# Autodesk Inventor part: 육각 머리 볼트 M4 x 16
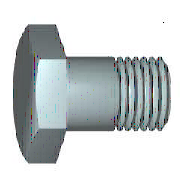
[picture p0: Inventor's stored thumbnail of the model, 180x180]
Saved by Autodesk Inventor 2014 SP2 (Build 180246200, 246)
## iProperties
IsCustomPart: 0
Created: 2012-02
Part Number: 육각 머리 볼트 M4 x 16
Material: 강철, 연강
Description: 6각 머리 볼트 및 6각 머리 나사
Document SubType Name: Modeling
Standard: KS B 1002
Designer: mduedu
Standards Organization: KS
Language: ko-KR
Size Designation: A + B M4 x 16
Categories: <MemberInstance><Categories><Category DisplayName="조임쇠" InternalName="e4da775c-781d-43d5-af7c-5136215cf5a6" Mnemonic="FSTN"><Category DisplayName="볼트" InternalN
Density: 7.86 g/cm^3
Appearance: 강철
Mass: 2.45486 g
Surface Area: 3.4613 cm^2
Volume: 0.312323 cm^3
Author: mduedu
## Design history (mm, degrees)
sketch "스케치1"
  geometry: L1 (0, 2.94)-(0, 2); L2 (2.1, 2)-(16, 2); L3 (16, 2)-(16, 0); L4 (16, 0)-(-0.4, 0); L5 (-3.68, 0)-(19.28, 0) reference; L6 (-0.4, 0)-(-0.4, 2.94); L7 (-0.4, 2.94)-(0, 2.94); L8 (2.1, 2)-(1.67, 2); L9 (1.67, 2)-(0, 2); L10 (0, -0.588)-(0, 3.528) reference
  constraints: 16 end point, 2 collinear, 2 perpendicular, 1 parallel
  dimensions: "d0" = 16 distance between parallel lines of L3 L1 (= NLG); "d1" = 13.9 distance from line of L2.start L3 (= GEL); "d2" = 4 diameter of L2 L4 (= GD); "d9" = 0.4001 distance between parallel lines of L6 L1 (computed from SD); "d10" = 5.88 diameter of L7 L4 (= SD2); "d13" = 0.42952 distance of L2.start L8.end (computed from GAL); "d14" = 4 diameter of L9 L4 (= BDM)
revolve "본체" sketch "스케치1" stored, may be unused: angle "d12" = 90 deg
sketch "스케치2"
  geometry: L1 (0, 4.041)-(3.5, 2.021); L2 (3.5, 2.021)-(3.5, -2.021); L3 (3.5, -2.021)-(0, -4.041); L4 (0, -4.041)-(-3.5, -2.021); L5 (-3.5, -2.021)-(-3.5, 2.021); L6 (-3.5, 2.021)-(0, 4.041); 2 further points
  constraints: 12 end point, 1 coincident, 1 vertical, 11 other
  dimensions: "d11" = 7 distance between parallel lines of L5 L2 (= SW)
extrude "머리" join sketch "스케치2" distance "d3" = 2.4 (= KOH - SD); taper "d4" = 0 deg
sketch "스케치4"
  geometry: L1 (-2.8, 3.5)-(-2.8, 4.041); L2 (-2.8, 4.041)-(-2.487, 4.041); L3 (-2.487, 4.041)-(-2.8, 3.5); L4 (-3.28, 0)-(0.08, 0) reference; L5 (-0.4, 4.041)-(-2.8, 4.041) reference; L6 (-2.8, 2.021)-(-2.8, 4.041) reference
  constraints: 6 end point, 2 collinear, 1 perpendicular, 1 vertical
  dimensions: "d5" = 30 deg angle of L3 L1 (= ANG1); "d19" = 7 diameter of L1.start L4 (= SW0)
revolve "모따기1" sketch "스케치4" stored, may be unused: angle "d21" = 90 deg
workplane "Work Plane1"
body "Solid1"
feature "스레드" dims "d15" = 13.9 (= GEL), "d16" = 0
chamfer "모따기2" distance "d6" = 0.42941 (= -0.5 x SPD + 0.5 x GD); stored, may be unused: second distance "d7" = 0.42952 (computed from GUL), angle "d55" = 45 deg
other parameters: "NLG" = 16 [user parameter; used in 1 equation term], "GD" = 4 (= NND) [user parameter; used in 2 equation terms], "BDM" = 4 (= NND) [user parameter; used in 1 equation term], "KOH" = 2.8 [user parameter; used in 1 equation term], "GEL" = 13.9 [user parameter; used in 2 equation terms], "SW" = 7 [user parameter; used in 3 equation terms], "SW0" = 7 (= SW) [user parameter; used in 1 equation term], "SPD" = 3.14117 (= NND - 1.2269 x PTC) [user parameter; used in 1 equation term], "SD2" = 5.88 (= SDH) [user parameter; used in 1 equation term], "SD" = 0.4 [user parameter; used in 2 equation terms], "ANG1" = 30 deg [user parameter; used in 1 equation term], "GAL" = 0.42941 (= 0.61345 x PTC) [user parameter; used in 1 equation term], "GUL" = 0.42941 (= 0.61345 x PTC) [user parameter; used in 1 equation term], "d8" = 0, "RR" = 0.2 [user parameter], "d57" = 0, "d58" = 0, "TPU" = 14.28571 (computed from PTC) [user parameter], "GD1" = 3.14117 (= THREADDIA - 1.2269 x PTC) [user parameter], "THREADDIA" = 4 [user parameter; used in 1 equation term], "SDH" = 5.88 [user parameter; used in 1 equation term], "SDHG" = 2.1 [user parameter], "TOA" = 30 deg [user parameter], "PTC" = 0.7 [user parameter; used in 5 equation terms], "NND" = 4 [user parameter; used in 3 equation terms], "E0" = 8.085 (= 1.155 x SW) [user parameter]
